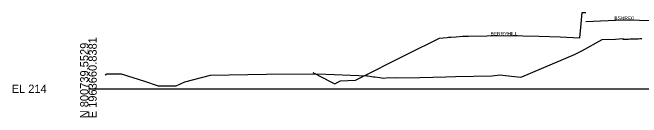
# Model space of a CAD drawing. Extents: x -26 to 403, y -10 to 6039.
# Drawn here: x -25.7 to 187.3, y 1990.3 to 2025.8 of the extents above; entities that cross this region are included whole.
import ezdxf

# ---------------------------------------------------------------- set-up
doc = ezdxf.new("R2010")
doc.units = 0
for name, color, linetype in [('Default', 7, 'Continuous'), ('RD_GPK_XS_Cell', 7, 'Continuous'), ('RD_TX_Misc1', 7, 'Continuous'), ('RD_XS_ExGround', 7, 'Continuous'), ('RD_XS_Pave', 7, 'Continuous')]:
    doc.layers.add(name, color=color, linetype=linetype)

msp = doc.modelspace()

# ---------------------------------------------------------------- linework, layer by layer
at = {"layer": 'RD_GPK_XS_Cell'}
msp.add_line((0, 2000), (200, 2000), dxfattribs=at)
at = {"layer": 'RD_XS_ExGround'}
msp.add_lwpolyline([(5.7, 2004.72), (6.23, 2005.09), (11.09, 2005.03), (19, 2002.6), (23.63, 2001.05), (25.77, 2001.04), (29.74, 2000.99), (32.71, 2002.37), (41.4, 2004.65), (60.32, 2004.93), (77.71, 2005.1), (94.26, 2004.4), (94.64, 2004.35), (96.56, 2004.09), (97.02, 2004.03), (98.77, 2003.79), (99.87, 2003.64), (101.78, 2003.82), (104.09, 2003.7), (112.28, 2003.82), (121.11, 2004.1), (124.3, 2004.16), (136.62, 2004.43), (139.53, 2004.7), (141.34, 2004.47), (146.38, 2003.97), (146.8, 2004), (164.71, 2011.61), (166.67, 2012.6), (167.14, 2012.85), (174.02, 2016.68), (178.59, 2016.81), (180.98, 2016.98), (181.09, 2016.76), (182.91, 2016.84), (183.56, 2016.86), (186.2, 2016.96), (186.76, 2016.98), (187.46, 2017)], dxfattribs=at)
at = {"layer": 'RD_XS_Pave'}
for points in [[(75.98, 2005.46), (82.37, 2002.23), (83.45, 2001.69), (84.47, 2002.2), (85.44, 2002.69), (87.99, 2002.81), (90.42, 2002.92), (107.96, 2011.69), (118.97, 2017.18), (120.17, 2017.28), (121.5, 2017.39), (121.99, 2017.42), (122.37, 2017.46), (122.72, 2017.48), (124.61, 2017.63), (126.72, 2017.8), (127.67, 2017.82), (128.72, 2017.84), (135.09, 2017.97), (140.72, 2018.08), (147.15, 2017.95), (152.73, 2017.83), (159.83, 2017.55), (166.49, 2017.28), (166.9, 2022), (167.24, 2025.79), (167.92, 2025.79), (168.49, 2025.79)], [(168.49, 2022.81), (181.08, 2023.32), (181.4, 2023.33), (197.41, 2023.02), (200.01, 2023.08)]]:
    msp.add_lwpolyline(points, dxfattribs=at)

# ---------------------------------------------------------------- texts
at = {"layer": 'Default'}
msp.add_text('-', height=0.0001, dxfattribs=at).set_placement((0, 2000))
at = {"layer": 'RD_GPK_XS_Cell'}
for s, p in [('N 800739.5529', (0, 1990)), ('E 1963660.8381', (2.8, 1990))]:
    msp.add_text(s, height=2.8, rotation=90, dxfattribs=at).set_placement(p)
msp.add_text('EL 214', height=2.8, dxfattribs=at).set_placement((-26, 1998.6))
at = {"layer": 'RD_TX_Misc1'}
for s, p in [('BSHRE0', (178.16, 2023.33)), ('BERRYHILL', (136.22, 2018.03))]:
    msp.add_text(s, height=1.2, dxfattribs=at).set_placement(p)

doc.saveas('drawing.dxf')
